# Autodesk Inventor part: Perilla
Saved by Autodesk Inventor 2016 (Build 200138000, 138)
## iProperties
Created: 2013-03
Part Number: Perilla
Material: Generic
Document SubType Name: Modeling
Designer: julian.chica
Density: 1 g/cm^3
Appearance: Default
Author: julian.chica
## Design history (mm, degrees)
derived "Parlante_INICIAL.ipt"
feature "Perilla::Parlante_INICIAL.ipt" dims "d0" = 10
tag "TaggingFeature1"
body "Solid1"
